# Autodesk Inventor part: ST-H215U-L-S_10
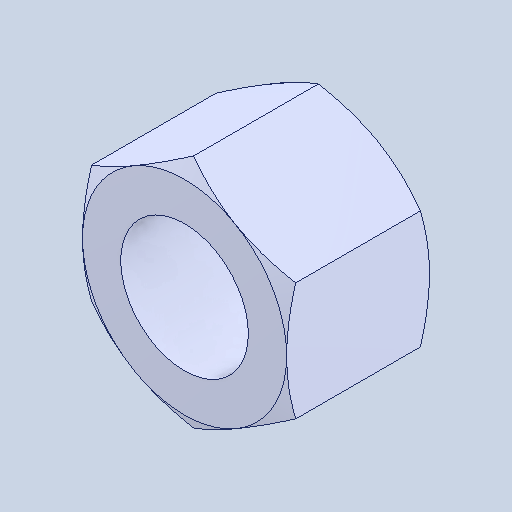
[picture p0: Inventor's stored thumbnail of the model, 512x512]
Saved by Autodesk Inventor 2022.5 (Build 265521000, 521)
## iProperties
Created: 2024-07
Part Number: ST-H215U-L-S_10
Material: 一般
Document SubType Name: Modeling
Designer: ImaoCorp
Density: 1 g/cm^3
Appearance: 既定
Author: ImaoCorp
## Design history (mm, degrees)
feature "ST-H215U-L-S_10"
node "ソリッド1"
